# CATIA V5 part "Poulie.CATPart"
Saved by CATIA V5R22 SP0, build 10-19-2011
Part number: Poulie
Bounding box of the stored display mesh (mm): x -12 to 12, y -11.856 to 11.856, z 0 to 12
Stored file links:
  U:\S9A\PER\CAO\Assemblage\Cadre\Chariot_X\Poulie.CATPart
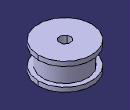
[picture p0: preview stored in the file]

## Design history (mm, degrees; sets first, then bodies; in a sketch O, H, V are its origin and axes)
Body1 (main body)
  Sketch1 on xy-plane, origin (0, 0, 0), H (1, 0, 0), V (0, 1, 0)
    circle A1 centre (0, 0) radius 12
    radius A1 = 12
  Pad1: profile Sketch1, direction (0, 0, 1), length 12
  Sketch2 on yz-plane, origin (0, 0, 0), H (0, 1, 0), V (0, 0, 1)
    line L1 (-12, 10) -> (-10, 10)
    line L2 (-10, 10) -> (-10, 2)
    line L3 (-10, 2) -> (-12, 2)
    line L4 (-12, 2) -> (-12, 10)
    reference projected line E1 (-12, 12) -> (12, 12) from edge [face of Pad1 from Sketch1.A1 | end face of Pad1]
    length L4 = 8
    length L3 = 2
    distance E1 L1 = 2
    distance V L4 = 12
    horizontal: L1 H, L3 H
    vertical: L2 V, L4 V
  Groove1: profile Sketch2, axis Sketch2.V, angle 360
  Sketch3 on start face of Pad1, origin (0, 0, 0), H (1, 0, 0), V (0, -1, 0)
    point P1 (0, 0)
    coincidence: P1 O
  Hole1: placed by Sketch3, at (0, 0, 0) direction (0, 0, 1), diameter 5, through (limit type 6)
